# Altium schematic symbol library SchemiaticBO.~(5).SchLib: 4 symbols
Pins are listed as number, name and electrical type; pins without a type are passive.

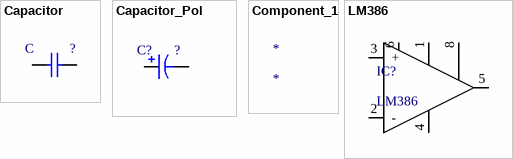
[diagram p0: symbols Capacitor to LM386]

## Capacitor
designator C  (value not drawn)
footprint SMD_0603_BO
footprint SMD_1206_BO
pins: 1, 2

## Capacitor_Pol
designator C?  (value not drawn)
footprint Panasonic_K16_BO
footprint CAP_POL_s16x25 (Raster 7.5)
footprint CAP_POL_s10x20 (Raster 5)
footprint CAP_POL_s10x16 (Raster 5)
footprint CAP_POL_s6.3x11 (Raster 2.5)
footprint CAP_POL_s5x11 (Raster 2)
footprint CAP_POL_SMD_6.8x6.8x8
footprint PANASONIC_B_BO
footprint PANASONIC_C_BO
footprint PANASONIC_D8_BO
pins: 1, 2

## Component_1
designator *

## LM386
designator IC?
footprint SO8_BO
pins: 1, 2 -, 3 +, 4, 5, 6, 8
